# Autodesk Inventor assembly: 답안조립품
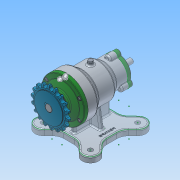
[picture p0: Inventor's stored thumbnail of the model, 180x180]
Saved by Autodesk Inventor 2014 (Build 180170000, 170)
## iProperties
Created: 2017-03
Part Number: 답안조립품
Document SubType Name: Assembly
Designer: NET
Author: NET
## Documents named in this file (14)
- C:\Users\NET\Desktop\470307v1025\답안조립품.iam
- C:\Users\NET\Desktop\470307v1025\본체.ipt
- C:\Users\NET\Desktop\470307v1025\앞커버.ipt
- C:\Users\NET\Desktop\470307v1025\뒤커버.ipt
- C:\Users\NET\Desktop\470307v1025\베어링-6203.ipt
- C:\Users\NET\Desktop\470307v1025\베어링-6200.ipt
- C:\Users\NET\Desktop\470307v1025\오일 실 17 30 8.ipt
- C:\Users\NET\Desktop\470307v1025\오일 실 10 20 7.ipt
- C:\Users\NET\Desktop\470307v1025\축.ipt
- C:\Users\NET\Desktop\470307v1025\키5x5.ipt
- C:\Users\NET\Desktop\470307v1025\스프로킷.ipt
- C:\Users\NET\Desktop\470307v1025\볼트 M4 x 12.ipt
- C:\Users\NET\Desktop\470307v1025\볼트 M5 x 10.ipt
- 볼트 M5 x 10.ipt
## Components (9 placed, 1 different names)
1. ISO 4762 M4 x 12:1
2. ISO 4762 M4 x 12:2
3. ISO 4762 M4 x 12:3
4. ISO 4762 M4 x 12:4
5. ISO 4762 M4 x 12:5
6. ISO 4762 M4 x 12:6
7. ISO 4762 M4 x 12:7
8. ISO 4762 M4 x 12:8
9. ISO 4762 M4 x 12:9
